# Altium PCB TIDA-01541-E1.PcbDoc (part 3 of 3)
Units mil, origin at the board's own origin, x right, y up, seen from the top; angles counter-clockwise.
Board outline 6299.21 x 6141.73 mil, 4 copper layers (Top Layer, GND, PWR, Bottom Layer), stack 79.834 mil thick; 369 components, 173 nets, 884 pads, 265 vias.
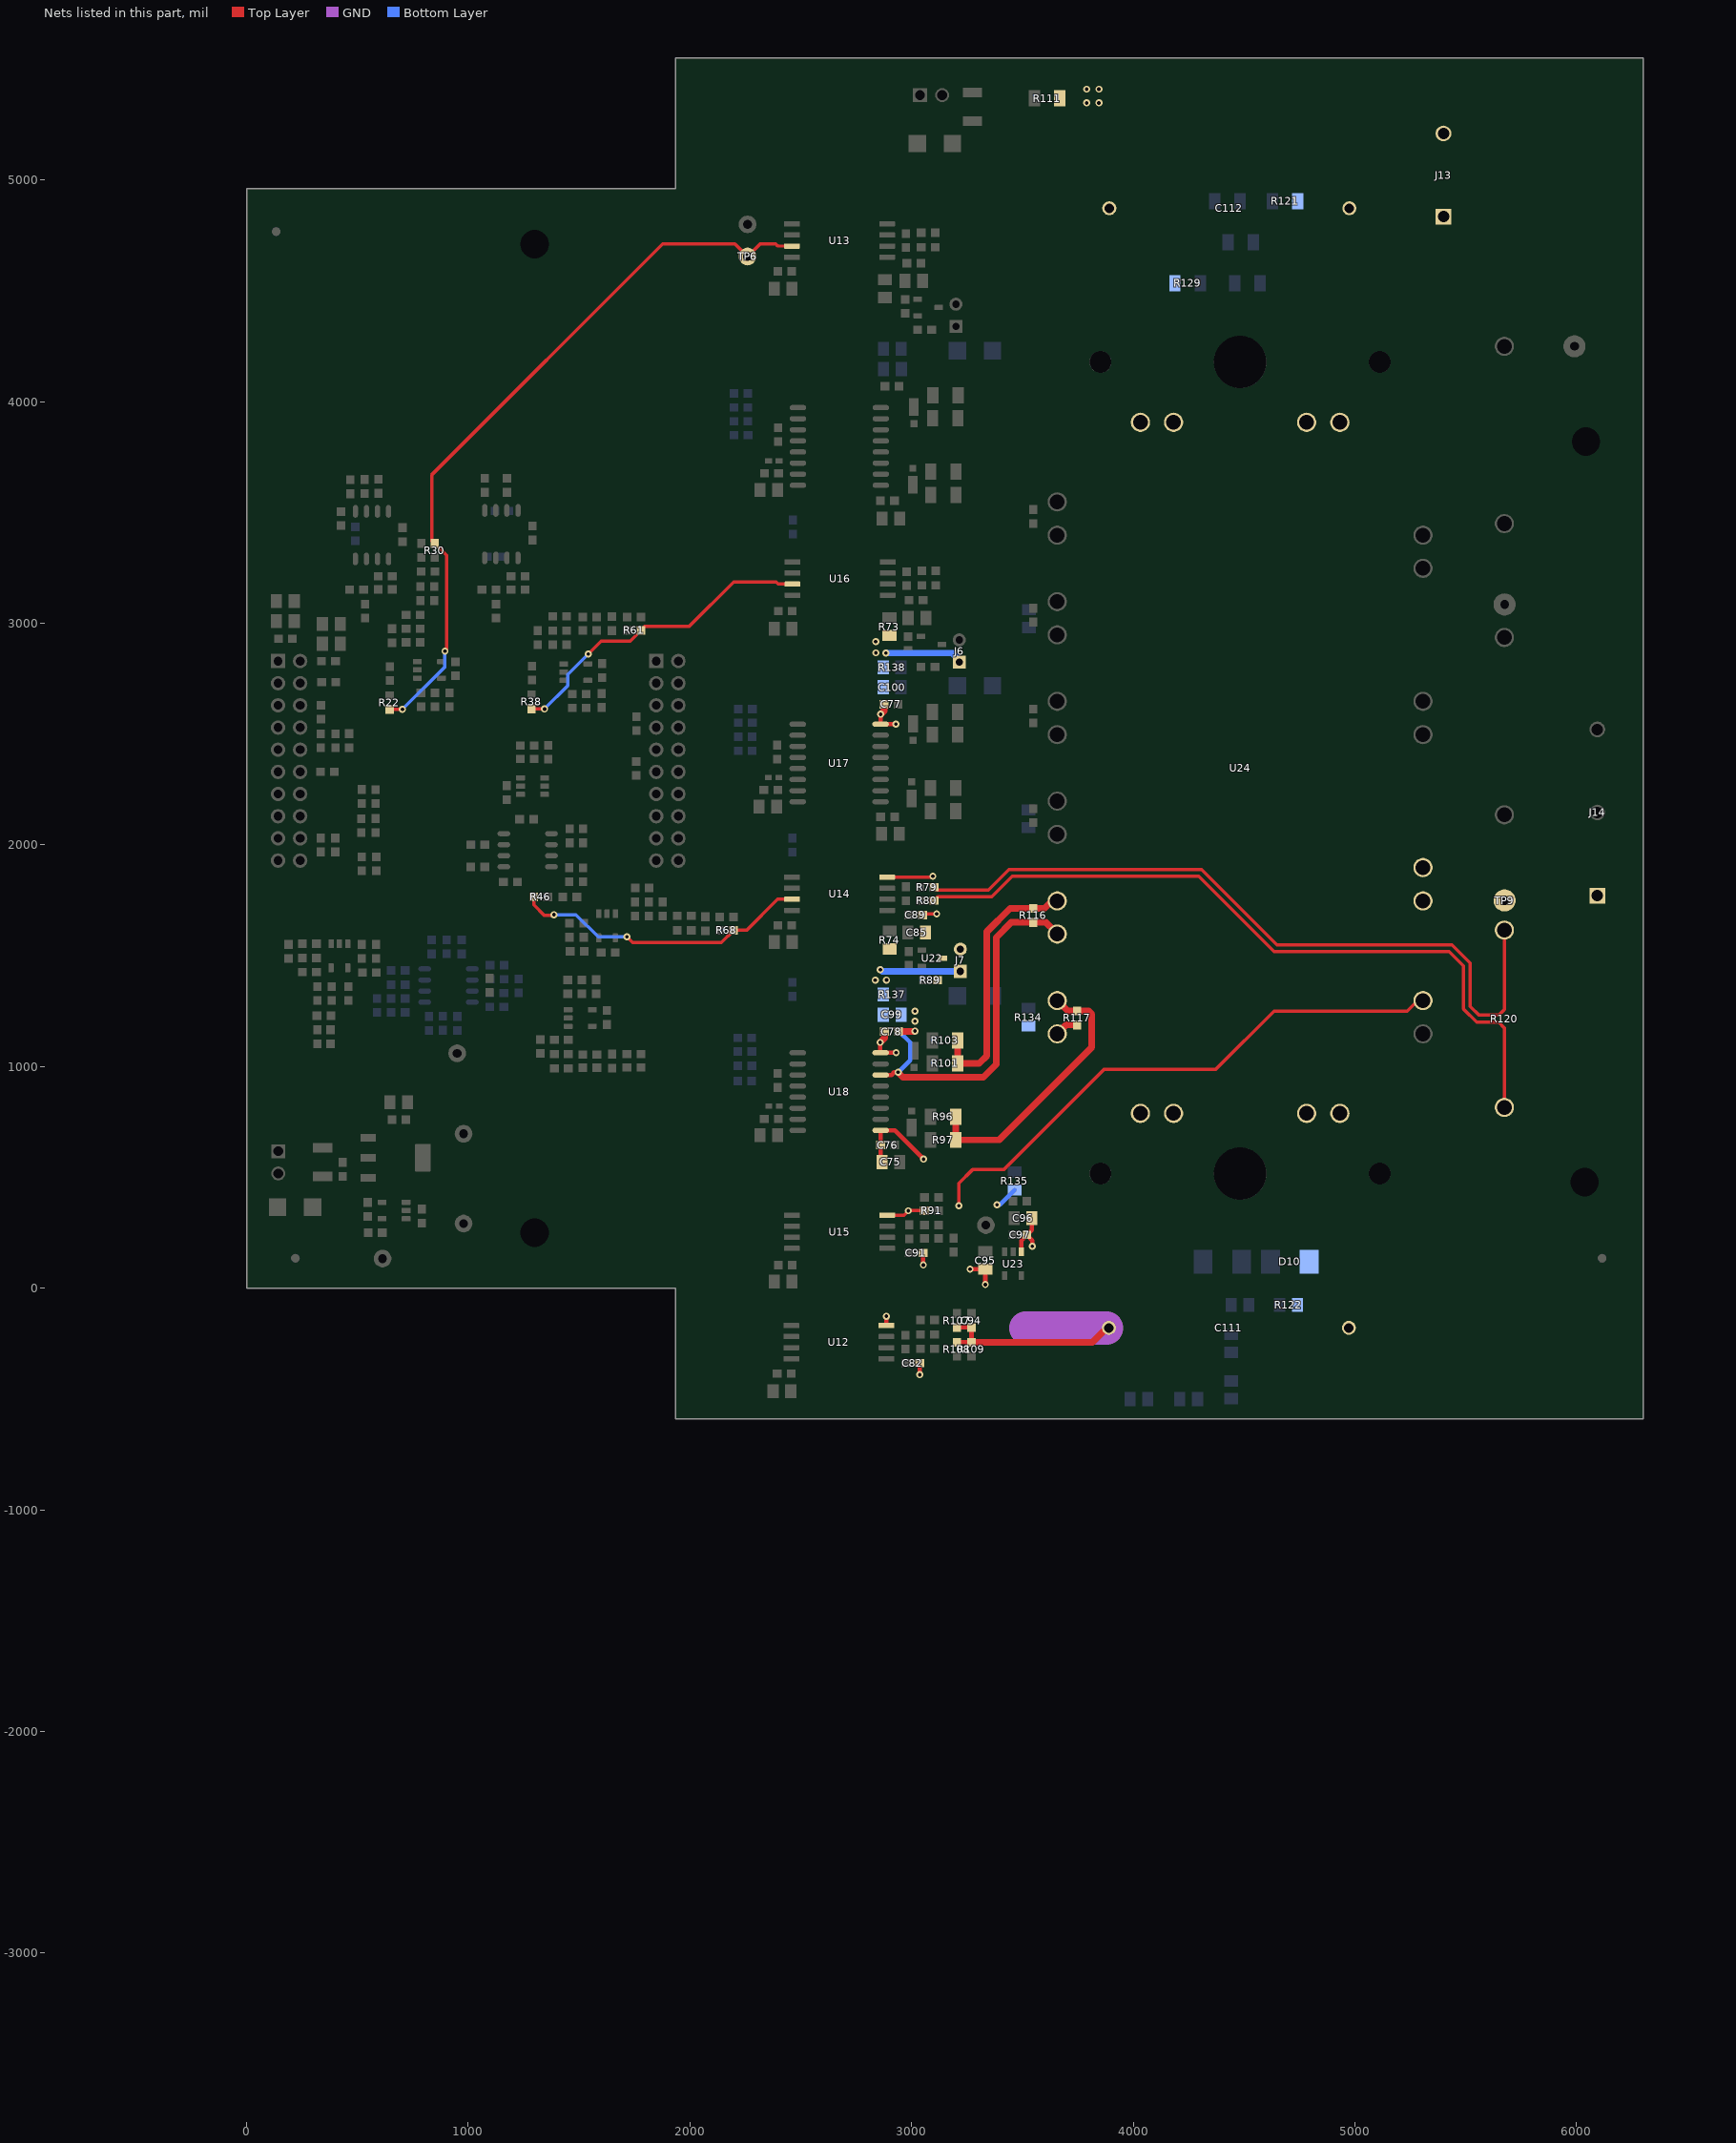
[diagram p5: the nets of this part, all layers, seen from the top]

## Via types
v1: diameter 32, hole 16, Top Layer to Bottom Layer, 258 vias
v2: diameter 24, hole 12, Top Layer to Bottom Layer, 7 vias

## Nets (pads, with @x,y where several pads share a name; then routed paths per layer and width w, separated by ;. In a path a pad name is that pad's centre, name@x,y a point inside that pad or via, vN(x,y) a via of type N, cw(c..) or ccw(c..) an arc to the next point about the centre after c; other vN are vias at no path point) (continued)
VCC_V: C77.2 C100.2 J6.1 R73.1 R138.1 U17.16 | length 526.2
  Top Layer w20: v1(2860,2589.19) U17.16@2860,2544.45 v1(2928.73,2544.45) v1@2931,2542.19
  Top Layer w30: v1(2860,2589.19) 2875.24,2604.43 C77.2@2875.24,2634.45
  Bottom Layer w30: v1(2883.73,2865.45) 3183.73,2865.45 J6.1@3224.73,2824.45
  other v1: 2838.73,2866.45 2837.73,2916.45
VCC_W: C78.2 C99.2 J7.1 R74.1 R137.1 U18.16 | length 539.5
  Top Layer w20: v1(2857.86,1108.86) 2857.86,1064.13 U18.16@2860.12,1061.86 2928.86,1061.86 v1(2929.86,1062.86)
  Top Layer w30: v1(2857.86,1108.86) 2877.37,1128.37 C78.2@2877.37,1157.86
  Bottom Layer w30: v1(2858.73,1437.45) 2866.73,1429.45 J7.1@3219.73,1429.45
  other v1: 2835.73,1389.45 2886.73,1390.45
VDC+: C111.1 C112.1 D10.1 J13.1 R121.1 R122.2 U24.15 U24.16 U24.25 U24.26 | length 2.8
  Top Layer w20: U24.15@4768.73,799.4 U24.15@4770.73,801.4
VDC-: C82.1 C91.1 C94.1 C95.2 C96.2 C97.2 C111.2 C112.2 J13.2 R91.1 R107.1 R108.1 R109.1 R111.2 R129.2 R135.1 U12.4 U15.4 U23.1 U24.13 U24.14 U24.18 U24.27 U24.28 | length 4556.1
  Top Layer w15: U15.4@2889.3,329.45 2964.73,329.45 v1(2984.73,349.45) R91.1@3058.24,349.45 ; v1(3212.73,372.45) 3212.73,472.88 3274.31,534.45 3415.31,534.45 3868.93,988.07 4373.07,988.07 4634.45,1249.45 5234.54,1249.45 U24.18@5295.54,1310.45
  Top Layer w20: v1(2885.73,-126.55) 2886.3,-127.12 U12.4@2886.3,-168.55 ; C82.1@3036.23,-338.55 3036.23,-390.05 v1(3036.73,-390.55) ; C91.1@3051.23,159.45 3051.23,105.95 v1(3052.73,104.45) ; R108.1@3204.73,-244.05 R109.1@3269.73,-244.05 C94.1@3269.73,-177.05 R107.1@3204.73,-177.05 ; v1(3263.33,85.32) C95.2@3332.33,85.32 ; v1(3332.33,16.32) C95.2@3332.33,85.32 ; C95.2@3346.47,99.45 C95.2@3332.33,85.32 ; U23.1@3494.73,164.45 3494.73,215.22 C97.2@3519.83,240.32 ; C96.2@3542.33,316.32 3542.33,262.82 C97.2@3519.83,240.32 ; v1(3544.73,189.45) 3544.73,215.41 C97.2@3519.83,240.32
  Top Layer w30: R109.1@3269.73,-244.05 3815.23,-244.05 C111.2@3879.73,-179.55
  GND w150: 3514.73,-179.55 C111.2@3879.73,-179.55
  Bottom Layer w20: v1@3383.73,377.45 v1(3384.73,376.45) 3397.73,376.45 R135.1@3464.73,443.45
  other v1: 3789.73,5347.45 3844.73,5347.45 3789.73,5409.45 3844.73,5409.45
VOUTP_U: R22.1 R30.1 TP6.1 U13.7 | length 3338.9
  Top Layer w15: R22.1@645,2610.5 702.5,2610.5 v1(703,2611) ; v1(894.73,2874.45) 901.73,2881.45 901.73,3306.82 R30.1@848.61,3359.95 834.73,3373.82 834.73,3668.73 1877.45,4711.45 2202.73,4711.45 TP6.1@2259.73,4654.45 2316.73,4711.45 2386.73,4711.45 2396.61,4701.58 U13.7@2460.17,4701.58
  Bottom Layer w15: v1(703,2611) 894.73,2802.73 v1(894.73,2874.45) v1@890.48,2874.45
VOUTP_V: R38.1 R61.1 U16.7 | length 1456.8
  Top Layer w15: R38.1@1285,2613.5 1335.5,2613.5 1336,2613 v1(1344,2613) ; v1(1541.53,2861.59) 1599.39,2919.45 1730.7,2919.45 R61.1@1779.25,2967.99 1798.05,2986.79 1998.08,2986.79 2197.48,3186.2 2389.08,3186.2 2398.95,3176.32 U16.7@2462.51,3176.32
  Bottom Layer w15: v1@1341,2610 v1(1344,2613) 1449,2718 1449,2769.06 v1(1541.53,2861.59) v1@1538.08,2861.59
VOUTP_W: R46.1 R68.1 U14.7 | length 1353
  Top Layer w15: R46.1@1295.5,1765 1295.5,1729.5 1342,1683 1384,1683 v1(1386,1685) ; v1(1715.96,1584.91) 1741.41,1559.45 2141.23,1559.45 R68.1@2196.23,1614.45 2254.73,1614.45 2394.73,1754.45 U14.7@2460.17,1754.45
  Bottom Layer w15: v1(1386,1685) 1485.86,1685 1585.96,1584.91 v1(1715.96,1584.91)
W_BOT: R96.2 R97.2 R117.2 U24.11 | length 1222.5
  Top Layer w30: R96.2@3199.2,773.86 R97.2@3199.2,668.86 3394.86,668.86 3813,1087 3813,1236 3798.5,1250.5 R117.2@3746,1250.5 3703.88,1250.5 U24.11@3656.93,1297.45
W_BOT_REF: C75.1 C76.1 R117.1 R134.1 U18.9 U24.12 | length 498.4
  Top Layer w20: C75.1@2865.86,568.86 2860.37,574.36 C76.1@2860.37,645.86 2860.12,646.1 U18.9@2860.12,711.86 2923.86,711.86 v1(3053.73,581.99)
  Top Layer w30: U24.12@3656.93,1147.45 3696.98,1187.5 R117.1@3746,1187.5
W_PHASE: J14.1 R80.1 R120.2 | length 3373.6
  Top Layer w15: R80.1@3101.23,1749.45 3117.23,1765.45 3360.73,1765.45 3453.73,1858.45 4295.73,1858.45 4634.73,1519.45 5424.73,1519.45 5489.73,1454.45 5489.73,1259.45 5549.73,1199.45 5647.73,1199.45 5673.73,1173.45 R120.2@5673.73,815.45
W_TOP: R101.2 R103.2 R116.2 U24.9 | length 1177.7
  Top Layer w30: R103.2@3208.2,1117.86 3208.2,1015.12 R101.2@3207.95,1014.86 3305.15,1014.86 3339.73,1049.45 3339.73,1608.95 3443.73,1712.95 R116.2@3548.73,1712.95 3598.43,1712.95 U24.9@3645.93,1760.45
W_TOP_REF: C78.1 C85.1 C89.1 C99.1 J7.2 R79.1 R89.2 R116.1 R120.1 TP9.1 U14.4 U18.14 U22.3 U24.10 U24.19 U24.20 | length 5382.8
  Top Layer w15: U14.4@2889.3,1854.45 3091.86,1854.45 v1(3095.73,1858.32) v1@3101.23,1852.83 ; C89.1@3049.23,1683.45 C89.1@3054.23,1688.45 ; 3071.91,1688.45 v1(3112.73,1688.45) ; R79.1@3101.23,1809.45 3115.23,1795.45 3345.73,1795.45 3438.73,1888.45 4308.16,1888.45 4647.16,1549.45 5437.16,1549.45 5519.73,1466.88 5519.73,1271.88 5560.16,1231.45 5647.73,1231.45 5673.73,1257.45 R120.1@5673.73,1615.45 ; U24.20@5294.54,1909.45 U24.20@5295.54,1910.45
  Top Layer w20: U18.14@2860.12,961.86 2908.86,961.86 2920.86,973.86 v1(2938.86,973.86)
  Top Layer w30: v1(2938.86,973.86) 2960.27,952.45 3323.73,952.45 3381.73,1010.45 3381.73,1582.45 3449.24,1649.95 R116.1@3548.73,1649.95 3606.43,1649.95 U24.10@3645.93,1610.45 ; C78.1@2940.36,1157.86 3012.86,1157.86 v1(3015,1160)
  Bottom Layer w20: v1(2938.86,973.86) 2992.86,1027.86 2992.86,1108.86 2943.86,1157.86 2940.36,1157.86
  other v1: 3015,1205 3015,1250
pads on no net: FID1.1 FID2.1 FID3.1 FID4.1 FID5.1 FID6.1 H1.1 H2.1 H3.1 H4.1 H5.0 H6.0 H7.0 H8.0 J2.3 J2.5 J2.7 J2.9 J2.11 J2.13 J2.15 J2.17 J2.19 J3.4 J3.8 J3.10 J3.14 J3.16 J3.17 J3.18 J3.19 J3.20 LBL1.0 U17.7 U17.12 U17.13 U18.7 U18.12 U18.13 U19.7 U19.12 U19.13 U23.4 U23.5 U24.MH1 U24.MH2 U24.MH3 U24.MH4 U24.MH5 U24.MH6

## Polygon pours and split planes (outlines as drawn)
V_TOP_REF on Top Layer "PWR-No Net" (solid, remove dead copper, pour order 127): 3034.73,3077.45 3034.73,2982.45 3036.34,2980.84 3071.18,2980.84 3080.15,2971.87 3085.73,2966.29 3085.73,2943.45 3085.73,2771.45 3066.73,2752.45 3002.73,2752.45 2984.73,2734.45 2984.73,2615.27 2995,2605 3035,2605 3044.73,2614.73 3044.73,2673.45 3050.73,2679.45 3147.73,2679.45 3161.73,2693.45 3161.73,3122.45 3154.73,3129.45 3039.73,3129.45 3034.73,3124.45
W_TOP_REF on Top Layer "Top Layer-No Net 1" (solid, remove dead copper, pour order 109): 3030.73,1711.45 3030.73,1574.45 3034.73,1570.45 3084.73,1570.45 3092.73,1562.45 3092.73,1358.45 2989.73,1255.45 2989.73,1145.27 3000,1135 3035,1135 3044.73,1144.73 3044.73,1224.45 3165.73,1345.45 3165.73,1712.45 3157.73,1720.45 3032.73,1720.45 3030.73,1718.45
NetC80_2 on Top Layer "Top Layer-No Net 1" (solid, remove dead copper, pour order 108): 3000.73,4655.45 2944.73,4655.45 2929.73,4670.45 2846.73,4670.45 2841.73,4665.45 2841.73,4521.45 2842.73,4522.45 2912.73,4522.45 2927.73,4522.45 2936.73,4513.45 2942.19,4507.99 2942.19,4448.45 2942.19,4438.99 2945.73,4435.45 3046.73,4435.45 3051.73,4440.45 3051.73,4477.5 3045.73,4483.5 3006.25,4483.5 3002.73,4487.02 3002.73,4636.45 3002.73,4653.45 3000.73,4655.45
U_TOP_REF on Top Layer "Top Layer-No Net 1" (solid, remove dead copper, pour order 110): 3018.73,4647.45 3018.73,4510.45 3022.73,4506.45 3049.73,4506.45 3067.73,4488.45 3067.73,4238.45 3000.73,4171.45 2977.73,4148.45 2977.73,4057.27 2985,4050 3030,4050 3039.73,4059.73 3039.73,4129.45 3153.73,4243.45 3153.73,4305.45 3153.73,4648.45 3145.73,4656.45 3020.73,4656.45 3018.73,4654.45
VCC_U on Top Layer "Top Layer-No Net 1" (solid, remove dead copper, pour order 112): 2834.73,4499.45 2915.73,4499.45 2919.73,4495.45 2919.73,4294.45 2909.73,4284.45 2839.73,4284.45 2832.73,4291.45 2832.73,4497.45
NetC86_2 on Top Layer "Top Layer-No Net 1" (solid, remove dead copper, pour order 114): 3009.73,3132.99 2938.19,3132.99 2931.73,3139.45 2926.73,3144.45 2865.73,3144.45 2853.73,3144.45 2850.73,3141.45 2850.73,2999.45 2857.73,2992.45 2940.73,2992.45 2949.73,2983.45 2956.53,2976.65 2956.53,2942.45 2956.53,2918.65 2961.73,2913.45 3060.73,2913.45 3065.73,2918.45 3065.73,2957.45 3062.73,2960.45 3025.79,2960.45 3023.73,2962.5 3012.73,2973.5 3012.73,3029.45 3012.73,3129.99 3009.73,3132.99
VCC_V on Top Layer "Top Layer-No Net 1" (solid, remove dead copper, pour order 115): 2937.73,2977.45 2830.73,2977.45 2824.73,2971.45 2819.73,2966.45 2819.73,2898.45 2819.73,2843.45 2823.73,2839.45 2930.73,2839.45 2939.73,2848.45 2939.73,2976.45 2938.73,2977.45
VCC_W on Top Layer "Top Layer-No Net 1" (solid, remove dead copper, pour order 117): 2859.73,1560.45 2938.73,1560.45 2940.73,1558.45 2940.73,1372.45 2934.73,1366.45 2823.73,1366.45 2818.73,1371.45 2818.73,1554.45 2824.73,1560.45
NetC85_2 on Top Layer "Top Layer-No Net 1" (solid, remove dead copper, pour order 118): 3009.73,1612.45 3009.73,1706.45 3007.73,1708.45 2945.73,1708.45 2932.73,1721.45 2911.73,1721.45 2850.73,1721.45 2848.73,1719.45 2848.73,1584.45 2851.73,1581.45 2943.73,1581.45 2954.73,1570.45 2959.53,1565.65 2959.53,1521.45 2959.53,1498.65 2963.73,1494.45 3065.73,1494.45 3069.73,1498.45 3069.73,1542.45 3066.73,1545.45 3015.98,1545.45 3014,1547.43 3009.73,1551.7 3009.73,1605.45
+16V_GPS on Top Layer "Top Layer-No Net 1" (solid, remove dead copper, pour order 102): 3344.73,5294.45 3109.73,5294.45 3104.73,5289.45 3104.73,5089.45 3109.73,5084.45 3558.73,5084.45 3576.73,5102.45 3576.73,5286.45 3568.73,5294.45
NetD8_2 on Top Layer "Top Layer-No Net 1" (solid, remove dead copper, pour order 103): 3074.73,5429.45 3074.73,5109.45 3069.73,5104.45 2984.73,5104.45 2979.73,5109.45 2973.76,5115.43 2973.76,5324.45 2973.76,5428.47 2979.73,5434.45 3069.73,5434.45 3074.73,5429.45
VDC- on Top Layer "Top Layer-No Net 1" (solid, remove dead copper, pour order 83): 3648.73,5319.45 3736.73,5319.45 3879.73,5319.45 3884.73,5324.45 3884.73,5429.45 3874.73,5439.45 3648.73,5439.45 3639.73,5430.45 3639.73,5328.45
GND1 on Top Layer "Top Layer-No Net 1" (solid, remove dead copper, pour order 74): 3110.73,5315.45 3570.73,5315.45 3579.73,5324.45 3579.73,5449.45 3568.73,5460.45 3109.73,5460.45 3102.73,5453.45 3102.73,5323.45
U_TOP_REF on Top Layer "Top Layer-No Net 1" (solid, remove dead copper, pour order 82): 5754.73,4304.45 5768.22,4290.96 5768.22,4259.45 5768.22,4202.94 5754.73,4189.45 5564.73,4189.45 5479.73,4104.45 5371.5,3996.21 5371.5,3594.45 5371.5,3201.21 5359.73,3189.45 5254.73,3189.45 5249.73,3194.45 5249.73,4029.45 5519.73,4299.45 5524.73,4304.45 5754.73,4304.45
V_TOP_REF on Top Layer "Top Layer-No Net 1" (solid, remove dead copper, pour order 78): 5254.73,2689.45 5254.73,2459.45 5264.73,2449.45 5361.5,2449.45 5371.5,2459.45 5371.5,2866.21 5389.73,2884.45 5759.73,2884.45 5764.73,2889.45 5764.73,2984.45 5749.73,2999.45 5269.73,2999.45 5254.73,2984.45
W_TOP_REF on Top Layer "Top Layer-No Net 1" (solid, remove dead copper, pour order 73): 5239.73,1944.45 5239.73,1714.45 5259.73,1694.45 5569.73,1694.45 5579.73,1684.45 5579.73,1584.45 5589.73,1574.45 5753.22,1574.45 5768.22,1589.45 5768.22,1740.96 5749.73,1759.45 5724.73,1784.45 5384.73,1784.45 5371.5,1797.69 5371.5,1799.45 5371.5,1937.69 5359.73,1949.45 5244.73,1949.45 5239.73,1944.45
NetD1_2 on Top Layer "Top Layer-No Net 1" (solid, remove dead copper, pour order 119): 183.73,553.45 98.73,553.45 93.73,548.45 93.73,313.45 93.73,308.45 98.73,303.45 188.73,303.45 193.73,308.45 193.73,543.45
GND on Top Layer "Top Layer-No Net 1" (solid, remove dead copper, pour order 107): 488.73,781.45 488.73,656.45 493.73,651.45 663.73,651.45 673.73,661.45 678.73,666.45 678.73,798.45 678.73,876.45 673.73,881.45 498.73,881.45 488.73,871.45
3V3 on Top Layer "Top Layer-No Net 1" (solid, remove dead copper, pour order 120): 698.73,878.45 698.73,633.45 683.73,618.45 518.73,618.45 508.73,608.45 508.73,563.45 513.73,558.45 678.73,558.45 688.73,548.45 693.73,543.45 698.73,538.45 698.73,503.45 698.73,475.5 713.73,460.5 870.78,460.5 878.73,468.45 878.73,878.45 868.73,888.45 703.73,888.45 698.73,883.45
5V0 on Top Layer "Top Layer-No Net 1" (solid, remove dead copper, pour order 123): 243.73,336.45 243.73,306.45 248.73,301.45 363.73,301.45 363.73,361.45 368.73,366.45 593.82,366.45 605.38,378.01 605.38,514.8 593.73,526.45 248.73,526.45 243.73,521.45
GND on Top Layer "Top Layer-No Net 1" (solid, remove dead copper, pour order 111): 108.73,576.45 358.73,576.45 393.73,541.45 457.28,541.45 462.28,546.45 462.28,712.91 453.73,721.45 443.73,731.45 228.73,731.45 103.73,731.45 98.73,726.45 93.73,721.45 93.73,581.45 98.73,576.45
V_BOT_REF on Bottom Layer "Top Layer-No Net 1" (solid, remove dead copper, pour order 138): 3152.73,2308.45 3443.73,2308.45 3453.73,2298.45 3453.73,2121.45 3464.73,2110.45 3685.73,2110.45 3694.73,2101.45 3694.73,2016.45 3687.73,2009.45 2830.73,2009.45 2819.73,2020.45 2819.73,2301.54 2826.65,2308.45 3152.73,2308.45
U_BOT_REF on Bottom Layer "Top Layer-No Net 1" (solid, remove dead copper, pour order 137): 3618.73,3004.45 3689.73,3004.45 3697.73,2996.45 3697.73,2919.45 3682.73,2904.45 3483.73,2904.45 3297.73,3090.45 3297.73,3396.45 3261.73,3432.45 2831.73,3432.45 2820.73,3443.45 2820.73,3729.45 2825.73,3734.45 3324.73,3734.45 3380.73,3678.45 3380.73,3218.45 3479.73,3119.45 3479.73,3021.45 3496.23,3004.95
W_BOT_REF on Bottom Layer "Top Layer-No Net 1" (solid, remove dead copper, pour order 135): 3501.73,1215.45 3690.73,1215.45 3695.73,1210.45 3695.73,1123.45 3687.73,1115.45 3585.73,1115.45 3577.73,1107.45 3577.73,552.45 3553.73,528.45 3478.73,528.45 2832.27,528.45 2819.86,540.86 2819.86,822.45 2823.86,826.45 3425.73,826.45 3444.73,845.45 3444.73,1203.45 3455.73,1214.45 3456.73,1215.45 3494.73,1215.45
W_TOP_REF on Bottom Layer "PWR-No Net" (solid, remove dead copper, pour order 121): 2914.86,949.86 3042.86,949.86 3046.86,953.86 3046.86,1261.86 3037.86,1270.86 2931.25,1270.86 2922.25,1261.86 2922.25,1137.11 2969.7,1089.67 2969.7,1036.7 2925.86,992.86 2911.78,978.78 2911.78,958.23 2911.78,952.94 2914.86,949.86
V_TOP_REF on Bottom Layer "PWR-No Net" (solid, remove dead copper, pour order 122): 2914.73,2432.45 3042.73,2432.45 3046.73,2436.45 3046.73,2744.45 3037.73,2753.45 2931.12,2753.45 2922.13,2744.45 2922.13,2619.7 2969.57,2572.25 2969.57,2519.29 2925.73,2475.45 2911.65,2461.37 2911.65,2440.82 2911.65,2435.53 2914.73,2432.45
U_TOP_REF on Bottom Layer "PWR-No Net" (solid, remove dead copper, pour order 124): 2915.73,3860.45 3043.73,3860.45 3047.73,3864.45 3047.73,4172.45 3038.73,4181.45 2932.12,4181.45 2923.13,4172.45 2923.13,4047.7 2970.57,4000.25 2970.57,3947.29 2926.73,3903.45 2912.65,3889.37 2912.65,3868.82 2912.65,3863.53 2915.73,3860.45
VCC_V on Bottom Layer "Top Layer-No Net 1" (solid, remove dead copper, pour order 104): 2824.73,2937.45 2820,2932.71 2820,2530.19 2828,2522.19 2945,2522.19 2953,2530.19 2953,2562.19 2911,2604.19 2904,2611.19 2904,2658.19 2904,2923.19 2889.73,2937.45
VCC_U on Bottom Layer "Top Layer-No Net 1" (solid, remove dead copper, pour order 113): 2827.73,3952.45 2943.73,3952.45 2951.73,3960.45 2951.73,3992.45 2942.73,4001.45 2902.73,4041.45 2902.73,4231.45 2902.73,4430.45 2890.73,4442.45 2830.73,4442.45 2818.73,4430.45 2818.73,3960.45 2826.73,3952.45
VCC_W on Bottom Layer "Top Layer-No Net 1" (solid, remove dead copper, pour order 116): 2825.73,1041.45 2943.73,1041.45 2950.73,1048.45 2950.73,1076.45 2901.73,1125.45 2901.73,1177.45 2901.73,1446.45 2893.73,1454.45 2827.73,1454.45 2818.73,1445.45 2818.73,1048.45
W_TOP_REF on Bottom Layer "Top Layer-No Net 1" (solid, remove dead copper, pour order 72): 5239.73,1944.45 5239.73,1714.45 5259.73,1694.45 5569.73,1694.45 5579.73,1684.45 5579.73,1584.45 5589.73,1574.45 5753.22,1574.45 5768.22,1589.45 5768.22,1740.96 5749.73,1759.45 5724.73,1784.45 5384.73,1784.45 5371.5,1797.69 5371.5,1799.45 5371.5,1937.69 5359.73,1949.45 5244.73,1949.45 5239.73,1944.45
V_TOP_REF on Bottom Layer "Top Layer-No Net 1" (solid, remove dead copper, pour order 77): 5254.73,2689.45 5254.73,2459.45 5264.73,2449.45 5361.5,2449.45 5371.5,2459.45 5371.5,2866.21 5389.73,2884.45 5759.73,2884.45 5764.73,2889.45 5764.73,2984.45 5749.73,2999.45 5269.73,2999.45 5254.73,2984.45
U_TOP_REF on Bottom Layer "Top Layer-No Net 1" (solid, remove dead copper, pour order 81): 5754.73,4304.45 5768.22,4290.96 5768.22,4259.45 5768.22,4202.94 5754.73,4189.45 5564.73,4189.45 5479.73,4104.45 5371.5,3996.21 5371.5,3594.45 5371.5,3201.21 5359.73,3189.45 5254.73,3189.45 5249.73,3194.45 5249.73,4029.45 5519.73,4299.45 5524.73,4304.45 5754.73,4304.45
VDC+ on Bottom Layer "Top Layer-No Net 1" (solid, remove dead copper, pour order 86): 5420.55,4949.45 4719.73,4949.45 4709.73,4939.45 4709.73,-210.55 4749.73,-250.55 5024.73,-250.55 5044.73,-230.55 5044.73,-105.55 4994.73,-55.55 4994.73,4499.45 5054.73,4559.45 5417.45,4559.45 5474,4616 5474,4896
VDC- on Bottom Layer "Top Layer-No Net 1" (solid, remove dead copper, pour order 92): 5475,5435 5475,5162 5417.45,5104.45 4269.73,5104.45 4224.73,5059.45 4224.73,-225.55 4199.73,-250.55 3829.73,-250.55 3814.73,-235.55 3814.73,-125.55 3934.73,-5.55 3934.73,4484.45 3764.73,4654.45 3764.73,5464.45 3789.73,5489.45 3794.73,5494.45 3869.73,5494.45 5415.55,5494.45
VCC_U on PWR "PWR-No Net" (solid, remove dead copper, pour order 129): 3246.73,4194.45 3246.73,3865.45 3239.73,3858.45 2825.73,3858.45 2821.73,3862.45 2820.73,3863.45 2820.73,3875.45 2820.73,4830.45 2839.73,4849.45 3226.73,4849.45 3242.73,4833.45 3246.73,4829.45 3246.73,4196.45
VCC_V on PWR "PWR-No Net" (solid, remove dead copper, pour order 131): 3246.73,2765.45 3246.73,2431.45 3241.73,2426.45 3238.73,2429.45 2862.73,2429.45 2827.32,2429.45 2819.73,2437.04 2819.73,3311.5 2830.69,3322.45 3224.73,3322.45 3237.73,3309.45 3246.73,3300.45 3246.73,2766.45
VCC_W on PWR "PWR-No Net" (solid, remove dead copper, pour order 133): 3247.73,1282.45 3247.73,953.45 3241.73,947.45 2823.86,947.45 2819.86,951.45 2819.86,1892.1 2824.34,1896.58 3225.61,1896.58 3242.73,1879.45 3247.73,1874.45 3247.73,1289.45
+16V_GPS on PWR "PWR-No Net" (solid, remove dead copper, pour order 134): 3324.73,4266.45 3324.73,3745.45 3313.73,3734.45 2825.65,3734.45 2820.73,3729.54 2820.73,3443.45 2831.73,3432.45 3284.73,3432.45 3322.73,3394.45 3324.73,3392.45 3324.73,2759.45 3324.73,2319.45 3313.73,2308.45 2826.65,2308.45 2819.73,2301.54 2819.73,2020.45 2830.73,2009.45 3300.73,2009.45 3316.73,1993.45 3324.73,1985.45 3324.73,1278.45 3324.73,868.45 3289.73,833.45 3282.73,826.45 2855.73,826.45 2823.86,826.45 2819.86,822.45 2819.86,540.86 2831.86,528.86 3547.15,528.86 3561.15,528.86 3575.73,543.45 3575.73,5488.45 3569.73,5494.45 3334.73,5494.45 3324.73,5484.45
W_TOP_REF on PWR "Top Layer-No Net 1" (solid, remove dead copper, pour order 71): 5239.73,1944.45 5239.73,1714.45 5259.73,1694.45 5569.73,1694.45 5579.73,1684.45 5579.73,1584.45 5589.73,1574.45 5753.22,1574.45 5768.22,1589.45 5768.22,1740.96 5749.73,1759.45 5724.73,1784.45 5384.73,1784.45 5371.5,1797.69 5371.5,1799.45 5371.5,1937.69 5359.73,1949.45 5244.73,1949.45 5239.73,1944.45
V_TOP_REF on PWR "Top Layer-No Net 1" (solid, remove dead copper, pour order 76): 5254.73,2689.45 5254.73,2459.45 5264.73,2449.45 5361.5,2449.45 5371.5,2459.45 5371.5,2866.21 5389.73,2884.45 5759.73,2884.45 5764.73,2889.45 5764.73,2984.45 5749.73,2999.45 5269.73,2999.45 5254.73,2984.45
U_TOP_REF on PWR "Top Layer-No Net 1" (solid, remove dead copper, pour order 80): 5754.73,4304.45 5768.22,4290.96 5768.22,4259.45 5768.22,4202.94 5754.73,4189.45 5564.73,4189.45 5479.73,4104.45 5371.5,3996.21 5371.5,3594.45 5371.5,3201.21 5359.73,3189.45 5254.73,3189.45 5249.73,3194.45 5249.73,4029.45 5519.73,4299.45 5524.73,4304.45 5754.73,4304.45
VDC+ on PWR "Top Layer-No Net 1" (solid, remove dead copper, pour order 85): 5423.55,4949.45 4719.73,4949.45 4709.73,4939.45 4709.73,-210.55 4749.73,-250.55 5024.73,-250.55 5044.73,-230.55 5044.73,-105.55 4994.73,-55.55 4994.73,4499.45 5054.73,4559.45 5417.45,4559.45 5471,4613 5471,4902
VDC- on PWR "Top Layer-No Net 1" (solid, remove dead copper, pour order 90): 5471,5438 5471,5155 5420.45,5104.45 4269.73,5104.45 4224.73,5059.45 4224.73,-225.55 4199.73,-250.55 3829.73,-250.55 3814.73,-235.55 3814.73,-125.55 3934.73,-5.55 3934.73,4484.45 3764.73,4654.45 3764.73,5464.45 3789.73,5489.45 3794.73,5494.45 3869.73,5494.45 5414.55,5494.45
3V3_VDC on PWR "Top Layer-No Net 1" (solid, remove dead copper, pour order 106): 2824.73,424.45 2824.73,-530.55 2844.73,-550.55 3544.73,-550.55 3559.73,-535.55 3559.73,404.45 3539.73,424.45 3527.47,436.72 2837,436.72
3V3 on PWR "Top Layer-No Net 1" (solid, remove dead copper, pour order 126): 2480,5495 1990,5495 1980,5485 1980,4945 1950,4915 45,4915 30,4900 30,55 45,40 1960,40 1980,20 1980,-540 1990,-550 2515,-550 2520,-545 2520,5490 2515,5495
GND1 on GND "Top Layer-No Net 1" (solid, remove dead copper, pour order 136): 3324.73,5484.45 3324.73,533.45 3329.73,528.45 3560.73,528.45 3575.73,543.45 3575.73,5488.45 3569.73,5494.45 3334.73,5494.45
W_TOP_REF on GND "PWR-No Net" (solid, remove dead copper, pour order 132): 3247.73,1282.45 3247.73,953.45 3241.73,947.45 2823.86,947.45 2819.86,951.45 2819.86,1892.1 2824.34,1896.58 3225.61,1896.58 3242.73,1879.45 3247.73,1874.45 3247.73,1289.45
V_TOP_REF on GND "PWR-No Net" (solid, remove dead copper, pour order 130): 3246.73,2765.45 3246.73,2431.45 3241.73,2426.45 3238.73,2429.45 2862.73,2429.45 2827.32,2429.45 2819.73,2437.04 2819.73,3311.5 2830.69,3322.45 3224.73,3322.45 3237.73,3309.45 3246.73,3300.45 3246.73,2766.45
U_TOP_REF on GND "PWR-No Net" (solid, remove dead copper, pour order 128): 3246.73,4194.45 3246.73,3865.45 3239.73,3858.45 2825.73,3858.45 2821.73,3862.45 2820.73,3863.45 2820.73,3875.45 2820.73,4830.45 2839.73,4849.45 3226.73,4849.45 3242.73,4833.45 3246.73,4829.45 3246.73,4196.45
VDC- on GND "Top Layer-No Net 1" (solid, remove dead copper, pour order 105): 2824.73,424.45 2824.73,-530.55 2844.73,-550.55 3544.73,-550.55 3559.73,-535.55 3559.73,404.45 3539.73,424.45 3527.47,436.72 2837,436.72
W_TOP_REF on GND "Top Layer-No Net 1" (solid, remove dead copper, pour order 70): 5239.73,1944.45 5239.73,1714.45 5259.73,1694.45 5569.73,1694.45 5579.73,1684.45 5579.73,1584.45 5589.73,1574.45 5753.22,1574.45 5768.22,1589.45 5768.22,1740.96 5749.73,1759.45 5724.73,1784.45 5384.73,1784.45 5371.5,1797.69 5371.5,1799.45 5371.5,1937.69 5359.73,1949.45 5244.73,1949.45 5239.73,1944.45
V_TOP_REF on GND "Top Layer-No Net 1" (solid, remove dead copper, pour order 75): 5254.73,2689.45 5254.73,2459.45 5264.73,2449.45 5361.5,2449.45 5371.5,2459.45 5371.5,2866.21 5389.73,2884.45 5759.73,2884.45 5764.73,2889.45 5764.73,2984.45 5749.73,2999.45 5269.73,2999.45 5254.73,2984.45
U_TOP_REF on GND "Top Layer-No Net 1" (solid, remove dead copper, pour order 79): 5754.73,4304.45 5768.22,4290.96 5768.22,4259.45 5768.22,4202.94 5754.73,4189.45 5564.73,4189.45 5479.73,4104.45 5371.5,3996.21 5371.5,3594.45 5371.5,3201.21 5359.73,3189.45 5254.73,3189.45 5249.73,3194.45 5249.73,4029.45 5519.73,4299.45 5524.73,4304.45 5754.73,4304.45
VDC+ on GND "Top Layer-No Net 1" (solid, remove dead copper, pour order 84): 5422.55,4949.45 4719.73,4949.45 4709.73,4939.45 4709.73,-210.55 4749.73,-250.55 5024.73,-250.55 5044.73,-230.55 5044.73,-105.55 4994.73,-55.55 4994.73,4499.45 5054.73,4559.45 5417.45,4559.45 5474,4616 5474,4898
VDC- on GND "Top Layer-No Net 1" (solid, remove dead copper, pour order 88): 5474,5435 5474,5158 5420.45,5104.45 4269.73,5104.45 4224.73,5059.45 4224.73,-225.55 4199.73,-250.55 3829.73,-250.55 3814.73,-235.55 3814.73,-125.55 3934.73,-5.55 3934.73,4484.45 3764.73,4654.45 3764.73,5464.45 3789.73,5489.45 3794.73,5494.45 3869.73,5494.45 5414.55,5494.45
GND on GND "Top Layer-No Net 1" (solid, remove dead copper, pour order 125): 2480,5495 1990,5495 1980,5485 1980,4945 1950,4915 45,4915 30,4900 30,55 45,40 1960,40 1980,20 1980,-540 1990,-550 2515,-550 2520,-545 2520,5490 2515,5495

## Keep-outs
Keep-Out Layer:
  text ".Layer_Name" at 111.73,-3325.04 h60

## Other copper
Top Layer:
  text ".layer_Name" at 126.73,-3314.55 h60
GND:
  text "GND" at 194.73,-3310.55 h60
PWR:
  region net W_PHASE: 5578.25,858.25 5578.25,781.76 5602.55,757.45 6093.45,757.45 6198,862 6198,1766 6131,1833 5945,1833 5883,1771 5883,1003 5762,882 5602,882
  region net U_PHASE: 6201,3424 6102,3523 5612,3523 5586,3497 5586,3403 5612,3377 5785,3377 5886,3276 5886,2532 5958,2460 6140,2460 6201,2521
  region net V_PHASE: 5586,2247 5586,2039 5641.27,1983.73 6142.55,1983.73 6201.55,2042.73 6201.55,2235.73 6138.55,2298.73 5637.73,2298.73
  text "PWR" at 204.73,-3310.55 h60
Bottom Layer:
  text ".Layer_Name" at 185.73,-3324.55 h60
Multi-Layer:
  pour cut-out: 2817.3,-545 2522.7,-545 2522.7,5500 2817.3,5500

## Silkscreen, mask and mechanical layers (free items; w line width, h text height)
Top Overlay:
  circle w10: c5989.73,4249.45 r70.51
  circle w10: c5674.73,3084.45 r70.51
  circle w10: c5674.73,1749.45 r70.51
  lines w6: 257.73,1311.4 281.73,1311.4 ; 276.73,1593.4 276.73,1638.4 ; 449.73,1629.45 454.73,1624.45 454.73,1594.45 ; 455.73,2867.45 463.73,2859.45 474.73,2859.45 ; 544.73,2479.45 504.73,2479.45 ; 545.93,2278.43 545.93,2290.64 553.74,2298.45 ; 550.73,803.45 567.73,803.45 583.53,787.65 626.75,787.65 ; 614.73,3074.45 624.73,3084.45 624.73,3109.45 ; 814.73,2549.45 814.73,2589.45 ; 1238.06,2935.12 1276.06,2935.12 ; 1354.73,2873.27 1354.73,2864.45 1474.06,2864.45 1474.06,2872.62 ; 1354.73,3069.45 1354.73,3094.45 1394.73,3134.45 1394.73,3249.45 1504.73,3249.45 1504.73,3119.45 1479.73,3094.45 1479.73,3069.45 ; 1379.73,1189.45 1419.73,1189.45 ; 1419.73,1609.45 1389.73,1609.45 ; 1424.73,3069.45 1424.73,3099.45 ; 1429.73,914.45 1429.73,944.45 ; 1483.5,1926.93 1483.5,1939.45 1492.96,1948.91 ; 1639.73,2784.45 1664.73,2784.45 ; 1659.73,1219.45 1689.73,1219.45 ; 2935.73,-372.55 2938.02,-372.55 2944.75,-365.82 ; 2950.73,125.45 2953.02,125.45 2959.75,132.18 ; 2955.73,333.45 2955.73,321.17 2962.47,314.43 ; 3069.72,4597.18 3119.47,4597.18 3127.73,4605.45 ; 3077.72,1656.18 3120.47,1656.18 3134.73,1670.45 ; 3079.72,3077.18 3130.47,3077.18 3136.73,3083.45 ; 3102.29,4483.5 3133.79,4515 3140,4515 ; 3116.29,2962.5 3124.5,2962.5 3152,2990 ; 3120.29,1547.5 3137.5,1547.5 3150,1560 3150,1595 3154,1599 3160,1605 ; 3131.72,-300.82 3131.72,-312.53 ; 3139.73,179.45 3149.72,189.43 3149.72,197.18 ; 3206,80.97 3216.93,91.9 3216.93,134.47 ; 276.73,1638.4 284.73,1630.4 268.73,1630.4 276.73,1638.4 ; 281.73,1311.4 274.73,1318.4 274.73,1301.4 281.73,1308.4 281.73,1311.4 ; 504.73,2479.45 514.73,2469.45 514.73,2489.45 504.73,2479.45 ; 814.73,2589.45 824.73,2579.45 804.73,2579.45 814.73,2589.45 ; 1389.73,1609.45 1399.73,1599.45 1399.73,1619.45 1389.73,1609.45 ; 1424.73,3099.45 1434.73,3089.45 1414.73,3089.45 1424.73,3099.45 ; 1429.73,944.45 1439.73,934.45 1419.73,934.45 1429.73,944.45 ; 3131.72,-312.53 3131.73,-312.55
  lines w10: -757.27,-3396.72 5842.73,-3396.72 ; -757.27,-3193.38 5844.73,-3193.38 ; -757.27,-2990.05 -757.27,-3600.05 3247.73,-3600.05 5844.73,-3600.05 ; -756.77,-3600.05 -756.77,-2990.05 5844.73,-2990.05 ; 1725.73,-3598.55 1725.73,-2988.55 ; 3934.73,-3194.88 3934.73,-2991.55 ; 4608.73,-3600.38 4608.73,-3397.55 ; 5844.23,-3600.05 5844.23,-2990.05
  text "GD_Supply" at 2530,5460 h50
  text "GND" at 3225,5460 h50
  text "VDC-" at 5927,5233 h50 r90
  text "600V DC" at 6182,4647 h100 r90
  text "VDC+" at 5939,4612 h50 r90
  text "DANGER HIGH VOLTAGE" at 4202,3265 h50
  text "U_PHASE" at 5968,2740 h50 r90
  text "V_PHASE" at 5855,2005 h50 r90
  text "DANGER HIGH VOLTAGE" at 4337,1990 h50
  text "W_PHASE" at 5962,1211 h50 r90
  text "DANGER HIGH VOLTAGE" at 4414,944 h50
  text "GND" at 85,700 h50 r90
  text "5V_VIN" at 75,155 h50 r90
  text ".layer_Name" at 152.73,-3312.55 h60
Bottom Overlay:
  lines w6: 699.73,1479.45 699.73,1519.45 ; 1026,1474 1026,1492 ; 1132.76,1494.45 1132.76,1539.45 ; 699.73,1519.45 709.73,1509.45 689.73,1509.45 699.73,1519.45 ; 1026,1492 1026,1491 1031,1486 1020,1486 1026,1492 ; 1132.76,1539.45 1133.76,1539.45 1140.76,1532.45 1125.76,1532.45 1132.76,1539.45
  text ".Layer_Name" at 111.73,-3325.04 h60
Top Paste:
  text ".Layer_Name" at 99.73,-3328.04 h60
Bottom Paste:
  text ".Layer_Name" at 99.73,-3328.04 h60
Top Solder:
  text ".Layer_Name" at 127.73,-3335.55 h60
Bottom Solder:
  text ".Layer_Name" at 174.73,-3331.55 h60
M1 Board Outline:
  the board outline again, w20
M2 Board Dimensions:
  rectangle: -645.5,-2646 -520.5,-2521
  rectangle: -520.5,-2771 -145.5,-2646
  lines w7: -645.5,-2646 354.5,-2646 ; -520.5,-2771 -520.5,-2521 ; -395.5,-2771 -395.5,-2521 ; -145.5,-2771 -145.5,-2521 ; 104.5,-2771 104.5,-2521 ; -645.5,-2771 354.5,-2771 354.5,-2521 -645.5,-2521 -645.5,-2771
  lines w10: -645.5,-2836 -645.5,-2816 ; -585.5,-2846 -645.5,-2826 ; -585.5,-2806 -645.5,-2826 ; -421.42,-2826 -645.5,-2826 ; 130.42,-2826 354.5,-2826 ; 294.5,-2846 354.5,-2826 ; 294.5,-2806 354.5,-2826 ; 354.5,-2836 354.5,-2816
  text "1000 (mil)" at -411.42,-2861.99 h60
M3 3D STEP Top:
  text ".Layer_Name" at 111.73,-3325.04 h60
M4 3D STEP Bottom:
  text ".Layer_Name" at 111.73,-3325.04 h60
M5 Assembly Top:
  circle w10: c3494.73,189.84 r11.18
  circle w10: c1424.73,1254.45 r11.18
  circle w10: c3084.73,1524.45 r8
  circle w10: c3079.73,2939.45 r8
  circle w10: c3064.73,4459.45 r8
  circle w10: c455,1575 r10.63
  circle w10: c1409.73,2816.52 r8.16
  circle w10: c749.73,2826.85 r8.16
  circle w10: c1663.36,1714.45 r8.16
  circle w10: c513.73,681.45 r8.16
  circle w10: c3199.73,4339.45 r8
  circle w10: c3214.73,2819.45 r8
  circle w10: c3219.73,1429.45 r8
  circle w10: c5989.73,4249.45 r70.51
  circle w10: c5674.73,3084.45 r70.51
  circle w10: c5674.73,1749.45 r70.51
  lines w6: -757.27,-3192.55 5846.73,-3192.55 ; -755.77,-3396.55 5848.73,-3396.55 ; 1725.73,-3598.05 1725.73,-2990.55 ; 2262.73,-3192.55 2262.73,-2990.05 ; 2974.73,-3189.88 2974.73,-2989.55 ; 3373.73,-3597.55 3373.73,-2990.05 ; 3934.73,-3189.55 3934.73,-2990.55 ; 5846.23,-3596.05 5846.23,-2990.05 -756.27,-2990.05 -756.27,-3598.55 5848.73,-3598.55 ; 6976.23,-2990.05 6978.73,-2992.55
  text "TP10" at 5949.73,4339.45 h25
  text "TP8" at 5639.73,3074.45 h25
  text "TP9" at 5629.73,1739.45 h25
  text "COMPONENTS MARKED 'DNP' SHOULD NOT BE POPULATED." at 688.23,-2785.05 h25
  text "ASSEMBLY VARIANT:" at 687.73,-2900.55 h25
  text ".VariantName" at 1723.73,-2900.55 h25
  text "ALL ARTWORK VIEWED FROM TOP SIDE" at -693.77,-3122.22 h25
  text "BOARD #:" at 1782.73,-3122.22 h25
  text ".PRJ_Number" at 2328.23,-3122.22 h25
  text "REV:" at 3172.73,-3122.22 h25
  text ".PCB_Rev" at 3464.23,-3122.22 h25
  text "SVN REV:" at 4010.73,-3122.22 h25
  text ".VersionControl_RevNumber" at 4516.73,-3122.22 h25
  text ".layer_Name" at 69.73,-3304.55 h25
  text ".PRJ_Number" at 2173.23,-3307.22 h25
  text "LAYER NAME =" at -700.27,-3311.55 h25
  text "TID #:" at 1797.73,-3312.22 h25
  text ".plot_File_Name" at -702.27,-3500.55 h25
  text "GENERATED    :" at 1784.73,-3530.88 h25
  text ".Print_Date" at 2654.23,-3530.88 h25
  text ".Print_Time" at 3383.23,-3530.88 h25
  text "TEXAS INSTRUMENTS" at 4647.73,-3530.88 h25
M6 Assembly Bottom:
  lines w6: -757.77,-3193.88 5844.23,-3193.88 ; -755.77,-3397.22 5844.23,-3397.22 ; 1380.73,-3193.38 1380.73,-2990.05 ; 1839.23,-3600.55 -757.77,-3600.55 -757.77,-2990.55 5843.73,-2990.55 ; 1839.23,-3600.05 5844.23,-3600.05 ; 2262.73,-3194.88 2262.73,-2991.55 ; 3373.73,-3600.55 3373.73,-2990.55 ; 4269.23,-3600.05 5844.73,-3600.05 ; 5844.23,-3600.55 5844.23,-2990.55 5844.23,-3600.55
  text "COMPONENTS MARKED 'DNP' SHOULD NOT BE POPULATED." at 5636.73,-2784.55 h25
  text ".VariantName" at 4592.73,-2900.55 h25
  text "ASSEMBLY VARIANT:" at 5631.73,-2900.55 h25
  text "SVN REV:" at 1076.23,-3122.72 h25
  text ".PCB_Rev" at 1622.73,-3122.72 h25
  text "REV:" at 1914.23,-3122.72 h25
  text ".PRJ_Number" at 2758.73,-3122.72 h25
  text "BOARD #:" at 3304.23,-3122.72 h25
  text "PCB VIEWED FROM BOTTOM SIDE" at 5780.73,-3122.72 h25
  text "Not in versioncontrol" at 735,-3125 h25
  text ".PRJ_Number" at 2921.77,-3303.22 h25
  text "LAYER NAME =" at 5775.73,-3307.55 h25
  text "TID #:" at 3297.27,-3308.22 h25
  text ".Layer_Name" at 5002.73,-3314.55 h25
  text "IGNORE ->" at 2082.58,-3325.04 h25
  text ".Print_Time" at 1703.73,-3531.38 h25
  text ".Print_Date" at 2432.73,-3531.38 h25
  text "GENERATED    :" at 3302.23,-3531.38 h25
  text ".plot_File_Name" at 4975.23,-3531.38 h25
  text "PLOT NAME =" at 5780.73,-3531.38 h25
M9 Title Sheet:
  drawing of 57 lines, arcs and shapes, not listed
  text "4" at 7771.24,10334.95 h70
  text "5" at 10270.23,10334.95 h70
  text "1" at 319.73,10329.45 h70
  text "2" at 2724.73,10324.45 h70
  text "3" at 5249.73,10324.45 h70
  text "6" at 12639.73,10324.45 h70
  text "A" at -881.77,4426.95 h70
  text "A" at 13918.23,4426.95 h70
  text "B" at -881.77,2046.95 h70
  text "B" at 13918.23,2046.95 h70
  text "C" at -881.77,-328.05 h70
  text "C" at 13918.23,-328.05 h70
  text "PROJECT TITLE:" at 10878.23,-2189.05 h45
  text ".PRJ_Title" at 11089,-2310 h70
  text "DESIGNED FOR:" at 10878.23,-2490.05 h45
  text ".PRJ_Customer" at 10928.23,-2630.05 h70
  text "D" at -881.77,-2698.05 h70
  text "D" at 13918.23,-2698.05 h70
  text "FILE NAME:" at 10878.23,-2790.05 h45
  text ".PCB_File_Name_No_Path" at 11209.73,-2915.55 h70
  text "Texas Instruments (TI) and/or its licensors do not warrant the accuracy or completeness of this specification" at 5908.73,-3071.89 h45
  text "ENGINEER:" at 10878.23,-3080.05 h45
  text "LAYOUT BY:" at 12383.23,-3080.05 h45
  text "or any information contained therein. TI and/or its licensors do not warrant that this design will meet" at 5863.75,-3184.55 h45
  text ".PRJ_Engineer" at 11127.23,-3209.55 h40
  text ".PCB_Layout" at 12632.73,-3209.55 h40
  text "the specifications, will be suitable for your application or fit for any particular purpose, or will operate in" at 5863.75,-3297.22 h45
  text "ALTIUM DESIGNER VERSION:" at 12383.23,-3390.05 h45
  text "an implementation. TI and/or its licensors do not warrant that the design is production worthy. You should" at 5863.75,-3409.88 h45
  text "completely validate and test your design implementation to confirm the system functionality for your application." at 5908.73,-3522.55 h45
  text ".print_Scale" at 10928.23,-3523.38 h70
  text ".Application_BuildNumber" at 12433.73,-3523.38 h70
  text "2" at 2770.23,-3730.05 h70
  text "3" at 5259.58,-3730.05 h70
  text "4" at 7766.24,-3730.05 h70
  text "5" at 10265.23,-3730.05 h70
  text "6" at 12770.23,-3730.05 h70
M10 Fab Notes:
  drawing of 228 lines, arcs and shapes, not listed
  text "DESIGN INFORMATION" at 11915.75,4343.45 h60
  text "(REFER ALSO ARRAY/PANEL PROFILING INFORMATION)" at 11554.19,4181.74 h60
  text "BOARD SIZE" at 10868.19,4177.45 h60
  text "160MM" at 11330.51,4049.63 h60
  text "X" at 11836.19,4049.63 h60
  text "156MM" at 12067.51,4049.63 h60
  text "Number of Layers :" at 11271.19,3852.45 h60
  text "4" at 12366,3842.45 h60
  text "MIN. TRACK WIDTH:" at 11271.19,3713.45 h60
  text "12" at 12367.43,3713.45 h60
  text "MIL" at 12522.19,3713.45 h60
  text "8" at 12369.73,3589.45 h60
  text "MIN. CLEARANCE:" at 11271.19,3581.45 h60
  text "MIL" at 12522.19,3581.45 h60
  text "16" at 12345,3465 h60
  text "MIN. VIA DRILL SIZE:" at 11271.19,3449.45 h60
  text "MIL" at 12522.19,3449.45 h60
  text "8 MIL" at 11966.19,3307.74 h60
  text "MINIMUM ANNULAR RING" at 10941.96,3303.46 h60
  text "EXTERNAL" at 12674.19,3303.46 h60
  text "PER" at 11141.96,3185.45 h60
  text "IPC-D-275 CLASS 2 LEVEL C" at 11361.96,3185.45 h60
  text "MIL, HOLES" at 12850.19,3073.16 h60
  text "+/-" at 12457.73,3072.45 h60
  text "+/-" at 13311.73,3072.45 h60
  text "REGISTRATION TOLERANCES:" at 10941.96,3067.45 h60
  text "METAL" at 12141.73,3067.45 h60
  text "5" at 12717.93,3067.45 h60
  text "3" at 13550.93,3067.45 h60
  text "MIL" at 13667.19,3067.45 h60
  text "MATERIAL:" at 10867.19,2857.99 h60
  text "FR-4 High Tg" at 11853.64,2717.66 h60
  text "FR-408" at 11288.19,2709.09 h60
  text "X" at 11694.73,2709.45 h60
  text "OTHER" at 12776.19,2709.09 h60
  text "63 MIL (1.6mm) +/-10%" at 11608.3,2546.37 h60
  text "THICKNESS:" at 10941.96,2542.09 h60
  text "X" at 11480.13,2542.09 h60
  text "OTHER" at 12893.19,2542.09 h60
  text "TOLERANCE:" at 10941.96,2384.09 h60
  text "X" at 11781.27,2384.09 h60
  text "ANSI IPC-6012 TYPE 3 CLASS 2" at 11968.21,2384.09 h60
  text "OTHER +/-" at 11968.19,2228.09 h60
  text "BOW & TWIST:" at 10941.96,2071.09 h60
  text "X" at 11781.27,2071.09 h60
  text "ANSI IPC-6012 TYPE 3 CLASS 2" at 11968.21,2071.09 h60
  text "OTHER +/-" at 11968.19,1912.58 h60
  text "COPPER THICKNESS (FINISHED):" at 10867.19,1777.09 h60
  text "1.4MIL (1oz)" at 11747.19,1624.37 h60
  text "2MIL (1.4oz)" at 12514.19,1624.37 h60
  text "2.8MIL (2oz)" at 13241.19,1624.37 h60
  text "OUTER:" at 11224.19,1620.09 h60
  text "X" at 11611.73,1616.45 h60
  text "X" at 11618.73,1474.45 h60
  text "1.4MIL (1oz)" at 11747.19,1467.37 h60
  text "2.8MIL (2oz)" at 12514.19,1467.37 h60
  text "N/A" at 13240.73,1467.74 h60
  text "INNER SIGNAL:" at 10935.11,1463.09 h60
  text "DRILLING:" at 10867.19,1324.09 h60
  text "REFERENCE:" at 10941.96,1207.09 h60
  text "X" at 11590.19,1207.09 h60
  text "AS SHOWN" at 11777.19,1207.09 h60
  text "X" at 12491.19,1207.09 h60
  text "NC_DRILL FILES" at 12628.19,1207.09 h60
  text "PTH MIN COPPER THICKNESS:" at 10941.96,1049.09 h60
  text "X" at 12292.19,1049.09 h60
  text "1MIL" at 12429.19,1049.09 h60
  text "OTHER" at 12926.19,1049.09 h60
  text "BOARD FINISH:" at 10867.19,890.09 h60
  text "SILKSCREEN:" at 11022.41,772.09 h60
  text "X" at 11971.19,772.09 h60
  text "TOP" at 12097.19,772.09 h60
  text "X" at 12481.19,772.09 h60
  text "BOTTOM" at 12608.19,772.09 h60
  text "SILKSCREEN COLOR:" at 11022.41,605.09 h60
  text "X" at 11970.15,605.09 h60
  text "WHITE" at 12097.19,605.09 h60
  text "OTHER" at 12608.19,605.09 h60
  text "SOLDER RESIST COLOR:" at 11022.41,435.09 h60
  text "X" at 11590.16,275.89 h60
  text "GREEN" at 11717.19,275.89 h60
  text "BLUE" at 12308.19,275.89 h60
  text "OTHER" at 12846.19,275.89 h60
  text "IMMERSION GOLD (ENIG)" at 11928.19,87.37 h60
  text "ENEPIG" at 13265.73,84.09 h60
  text "SURFACE FINISH:" at 10867.19,83.09 h60
  text "X" at 11741.25,83.09 h60
  text "IMM. TIN/SILVER OR EQUIV" at 11196.73,-73.91 h60
  text "OTHER" at 12628.19,-73.91 h60
  text "ARRAY/PANEL:" at 10867.19,-252.91 h60
  text "CUT AND TRIM PER MECH LAYER 1" at 11928.19,-257.2 h60
  text "N.C. ROUTE" at 11928.19,-408.91 h60
  text "X" at 12607.19,-408.91 h60
  text "V. SCORE" at 12794.19,-408.91 h60
  text "CERTIFICATION:" at 10867.19,-545.91 h60
  text "MATERIALS AND WORKMANSHIP FOR ALL PCBS" at 11592.19,-545.91 h60
  text "TO MEET OR EXCEED THE REQUIREMENTS OF:" at 11592.19,-643.91 h60
  text "X" at 11218.7,-780.41 h60
  text "ANSI IPC-A-600F CLASS ->" at 11357.7,-780.41 h60
  text "X" at 12996.75,-780.41 h60
  text "2" at 13115.7,-780.41 h60
  text "1" at 12800.7,-781.91 h60
  text "3" at 13469.7,-781.91 h60
  text "X" at 11220.75,-939.91 h60
  text "UL 94V-0" at 11357.7,-939.91 h60
  text "X" at 12032.75,-939.91 h60
  text "RoHS" at 12169.7,-939.91 h60
  text "OTHER" at 12814.1,-939.91 h60
  text "PER ORDER" at 13211.16,-939.91 h60
  text "VIA TENTING:" at 12084.73,-1073.55 h60
  text "X" at 13164.73,-1075.55 h60
  text "ADDITIONAL REQUIREMENTS:" at 10867.19,-1080.91 h60
  text "YES" at 12634.4,-1082.63 h60
  text "NO" at 12999.21,-1087.86 h60
  text "MICROSECTION:" at 10941.96,-1195.91 h60
  text "YES" at 11847.7,-1195.91 h60
  text "IMPEDANCE CONTROL:" at 12106.73,-1202.55 h60
  text "YES" at 13090.73,-1203.55 h60
  text "X" at 13632.73,-1210.55 h60
  text "NO" at 13466.21,-1220.86 h60
  text "REQUIRED" at 12709.19,-1352.05 h60
  text "BARE BOARD ELEC. TEST:" at 10941.96,-1354.91 h60
  text "NONE" at 12247.7,-1354.91 h60
  text "X" at 12582.19,-1354.91 h60
  text "PER ORDER" at 13301.19,-1354.91 h60
  text "MANUFACTURER'S UL:" at 10941.96,-1511.91 h60
  text "RAIL" at 12107.7,-1516.2 h60
  text "METAL" at 12599.51,-1516.2 h60
  text "X" at 12974.73,-1516.55 h60
  text "SILK" at 13111.19,-1516.2 h60
M11 Gerber Information:
  lines w10: -758.27,-3600.05 3246.73,-3600.05 ; -757.27,-3600.05 -757.27,-2990.05 ; -757.27,-3396.72 5842.73,-3396.72 ; -757.27,-3193.38 5844.73,-3193.38 ; -756.77,-3600.05 -756.77,-2990.05 5844.73,-2990.05 5844.73,-3600.05 3247.73,-3600.05 ; 1725.73,-3598.55 1725.73,-2988.55 ; 4608.73,-3600.38 4608.73,-3397.55 ; 3934.73,-3194.88 3934.73,-2991.55 3934.73,-3194.88
  text "BOARD #:" at 1782.73,-3122.22 h60
  text ".PRJ_Number" at 2328.23,-3122.22 h60
  text "REV:" at 3172.73,-3122.22 h60
  text ".PCB_Rev" at 3464.23,-3122.22 h60
  text "SVN REV:" at 4010.73,-3122.22 h60
  text ".VersionControl_RevNumber" at 4516.73,-3122.22 h60
  text "ALL ARTWORK VIEWED FROM TOP SIDE" at -694.77,-3128.22 h60
  text "LAYER NAME =" at -696.27,-3311.55 h60
  text "TID #:" at 1787.73,-3317.22 h60
  text ".PRJ_Number" at 2153.23,-3317.22 h60
  text ".plot_File_Name" at -704.27,-3510.55 h60
  text "GENERATED    :" at 1784.73,-3530.88 h60
  text ".Print_Date" at 2654.23,-3530.88 h60
  text ".Print_Time" at 3383.23,-3530.88 h60
  text "TEXAS INSTRUMENTS" at 4647.73,-3530.88 h60
M12 Stackup:
  lines w6: 10894.73,4993.45 13444.73,4993.45 ; 10894.73,5097.85 13444.73,5097.85 ; 10834.73,4508.45 ccw(c10868.73,4508.45) 10868.73,4474.45 13470.73,4474.45 ccw(c13470.73,4508.45) 13504.73,4508.45 13504.73,5214.45 ccw(c13470.73,5214.45) 13470.73,5248.45 10868.73,5248.45 ccw(c10868.73,5214.45) 10834.73,5214.45 10834.73,4508.45
  text "Layer Stack Up Detail for: TIDA-00366-E2" at 10894.73,5130.55 h57
  text "Layer" at 10894.73,5058.85 h24
  text "Gerber" at 11790.55,5058.85 h24
  text "Copper" at 12354.07,5058.85 h24
  text "Dielectric" at 12956.77,5058.85 h24
  text "Name" at 10894.73,5010.85 h24
  text "Document" at 11790.55,5010.85 h24
  text "Thickness" at 12354.07,5010.85 h24
  text "Material" at 12956.77,5010.85 h24
  text "Top Solder Mask" at 10909.73,4919.45 h34
  text "(.GTS)" at 11790.55,4917.89 h34
  text "Solder Resist" at 12956.77,4917.89 h34
  text "Top Layer" at 10904.73,4824.45 h34
  text "(.GTL)" at 11790.55,4821.14 h34
  text "1.4mil" at 12354.07,4821.14 h34
  text "FR4-High Tg" at 12985.73,4820.45 h34
  text "FR4-High Tg" at 12990.73,4765.45 h34
  text "1.4mil" at 12354.07,4756.14 h34
  text "GND" at 10903.73,4752.45 h34
  text "(.G1)" at 11789.55,4744.14 h34
  text "FR4-High Tg" at 12990.73,4690.45 h34
  text "1.4mil" at 12354.07,4686.14 h34
  text "(.G2)" at 11789.55,4674.14 h34
  text "PWR" at 10903.73,4672.45 h34
  text "FR4-High Tg" at 12990.73,4595.45 h34
  text "Bottom Layer" at 10899.73,4594.45 h34
  text "(.GBL)" at 11798.73,4590.45 h34
  text "1.4mil" at 12358.73,4584.45 h34
  text "Solder Resist" at 12950.73,4517.45 h34
  text "(.GBS)" at 11795.73,4510.45 h34
  text "Bottom Solder Mask" at 10904.73,4509.45 h34
M13 Component Bodies Top:
  text ".Layer_Name" at 111.73,-3325.04 h60
M14 Component Bodies Bottom:
  text ".Layer_Name" at 111.73,-3325.04 h60
M15 Courtyards Top:
  text ".Layer_Name" at 111.73,-3325.04 h60
M16 Courtyards Bottom:
  text ".Layer_Name" at 111.73,-3325.04 h60
Drill Drawing:
  text ".legend" at 4695,8889 h60
  text "Drill Table" at 4735,6810 h60
  text "FOR 16MIL DRILL +0/-16MIL" at 4735,6690 h60
  text "FOR PTH DRILL +/-3MIL" at 4730.73,6598.45 h60
  text "FOR NPTH DRILL +/-2MIL" at 4735,6515 h60
  text ".layer_Name" at 216.73,-3308.55 h60

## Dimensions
0,0 to 0,4960.63 on M2 Board Dimensions
0,4960.63 to 1934.73,4960.63 on M2 Board Dimensions
1934.73,0 to 1934.73,-590.55 on M2 Board Dimensions
0,0 to 6299.21,-590.55 on M2 Board Dimensions
6299.21,5551.18 to 6299.21,-590.55 on M2 Board Dimensions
